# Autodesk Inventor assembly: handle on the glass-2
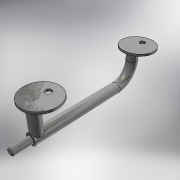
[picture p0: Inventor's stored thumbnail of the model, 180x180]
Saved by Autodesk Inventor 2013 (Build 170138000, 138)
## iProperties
Shininess: 64.0
Length Units: 11269
Angle Units: 11279
Time Units: 11290
Mass Units: 11283
Length Display Precision: 3
Angle Display Precision: 2
Compacted: True
Created: 2005-02
Part Number: handle on the glass-2
Document SubType Name: Assembly
Designer: =<Author>
Manufacturer: Standard
Standards Organization: Custom
Description: =<Part Number>
Mass: 258.326 g
Surface Area: 310.021 cm^2
Volume: 33.3323 cm^3
Density: 7.75 g/cm^3
Density: 0.0
Volumn: 0.0
Area: 0.0
PropertySet Name: Model Information
Control State: 0
Master: False
Checked Out: False
Checked Out Date: 2008-10-15
Last Check In Date: 2008-10-15
Author: PVitaliy
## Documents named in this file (5)
- Y:\Dropbox\Launch 2013\Eco Material Advisor\Assy, Door\_Data\Assy, Cab\handle on the glass-2.iam
- Y:\Dropbox\Launch 2013\Eco Material Advisor\Assy, Door\_Data\Assy, Cab\handle on the glass-2.ipt
- Y:\Dropbox\Launch 2013\Eco Material Advisor\Assy, Door\_Data\Assy, Cab\clamp.ipt
- Y:\Dropbox\Launch 2013\Eco Material Advisor\Assy, Door\_Data\Assy, Cab\support for a new pen.ipt
- Y:\Dropbox\Launch 2013\Eco Material Advisor\Assy, Door\_Data\Assy, Cab\stand.ipt
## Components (5 placed, 4 different names)
1. support for a new pen:1 — Flush:1, Mate:2, Mate:3, Mate:6
2. handle on the glass-2:1 — Insert:1, Mate:1, Flush:1, Mate:2, Mate:3, Flush:2
3. clamp:1 — Insert:1
4. stand:1 — Mate:1, Mate:4, Mate:5
5. support for a new pen:2 — Mate:4, Flush:2, Mate:5, Mate:6
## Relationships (9: Mate 6, Flush 2, Insert 1)
- Insert:1: handle on the glass-2:1 ↔ clamp:1
- Mate:1: handle on the glass-2:1 ↔ stand:1
- Flush:1: support for a new pen:1 ↔ handle on the glass-2:1
- Mate:2: support for a new pen:1 ↔ handle on the glass-2:1
- Mate:3: support for a new pen:1 ↔ handle on the glass-2:1
- Mate:4: stand:1 ↔ support for a new pen:2
- Flush:2: handle on the glass-2:1 ↔ support for a new pen:2
- Mate:5: stand:1 ↔ support for a new pen:2
- Mate:6: support for a new pen:1 ↔ support for a new pen:2
